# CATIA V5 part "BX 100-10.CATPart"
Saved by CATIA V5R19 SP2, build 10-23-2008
Part number: BX 100-10
Bounding box of the stored display mesh (mm): x -18.951 to 18.951, y -18.952 to 18.952, z 0 to 75
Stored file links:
  C:\Users\Bora\Desktop\3D Katı model\BX serisi\BX 100\BX 100-10.CATPart
  C:\Program Files\Dassault Systemes\B19\intel_a\reffiles\standard\MetricThickPitch.txt
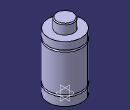
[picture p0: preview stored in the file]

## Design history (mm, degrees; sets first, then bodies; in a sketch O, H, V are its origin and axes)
Body1 (main body)
  Sketch1 on yz-plane, origin (0, 0, 0), H (0, 1, 0), V (0, 0, 1)
    point P2 (19, 9.5)
    line L1 (19, 9.5) -> (19, 0)
    point P3 (19, 9.5)
    point P4 (19, 11.5)
    arc A1 centre (19, 10.5) radius 1 from (19, 11.5) to (19, 9.5) ccw
    point P5 (19, 11.5)
    point P6 (19, 53.5)
    line L2 (19, 53.5) -> (19, 11.5)
    point P7 (19, 53.5)
    point P8 (19, 55.5)
    arc A2 centre (19, 54.5) radius 1 from (19, 55.5) to (19, 53.5) ccw
    point P10 (10, 74)
    arc A3 centre (9, 74) radius 1 from (10, 74) to (9, 75) ccw
    point P12 (10, 74)
    line L3 (10, 74) -> (10, 64)
    point P14 (19, 55.5)
    line L4 (19, 64) -> (19, 55.5)
    line L5 (0, 75) -> (9, 75)
    line L6 (10, 64) -> (19, 64)
    line L7 (0, 0) -> (19, 0)
    horizontal: L5 H, L6 H, L7 H
    coincidence: P2 P3, P4 P5, P6 P7, P8 P14, P10 P12
  Shaft1: profile Sketch1, axis Sketch1.V, angle 360
  Sketch2 on face of Shaft1 from Sketch1.L7, origin (0, 0, 0), H (1, 0, 0), V (0, -1, 0)
    point P1 (9, 0)
    distance P1 V = 9
  Hole1: placed by Sketch2, at (9, 0, 0) direction (0, 0, 1), diameter 4.917, depth 6, threaded "M6", thread diameter 6, thread depth 6, pitch 1
  Sketch3 on face of Shaft1 from Sketch1.L7, origin (0, 0, 0), H (1, 0, 0), V (0, -1, 0)
    point P1 (-9, 0)
    distance P1 V = 9
  Hole2: placed by Sketch3, at (-9, 0, 0) direction (0, 0, 1), diameter 4.917, depth 6, threaded "M6", thread diameter 6, thread depth 6, pitch 1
